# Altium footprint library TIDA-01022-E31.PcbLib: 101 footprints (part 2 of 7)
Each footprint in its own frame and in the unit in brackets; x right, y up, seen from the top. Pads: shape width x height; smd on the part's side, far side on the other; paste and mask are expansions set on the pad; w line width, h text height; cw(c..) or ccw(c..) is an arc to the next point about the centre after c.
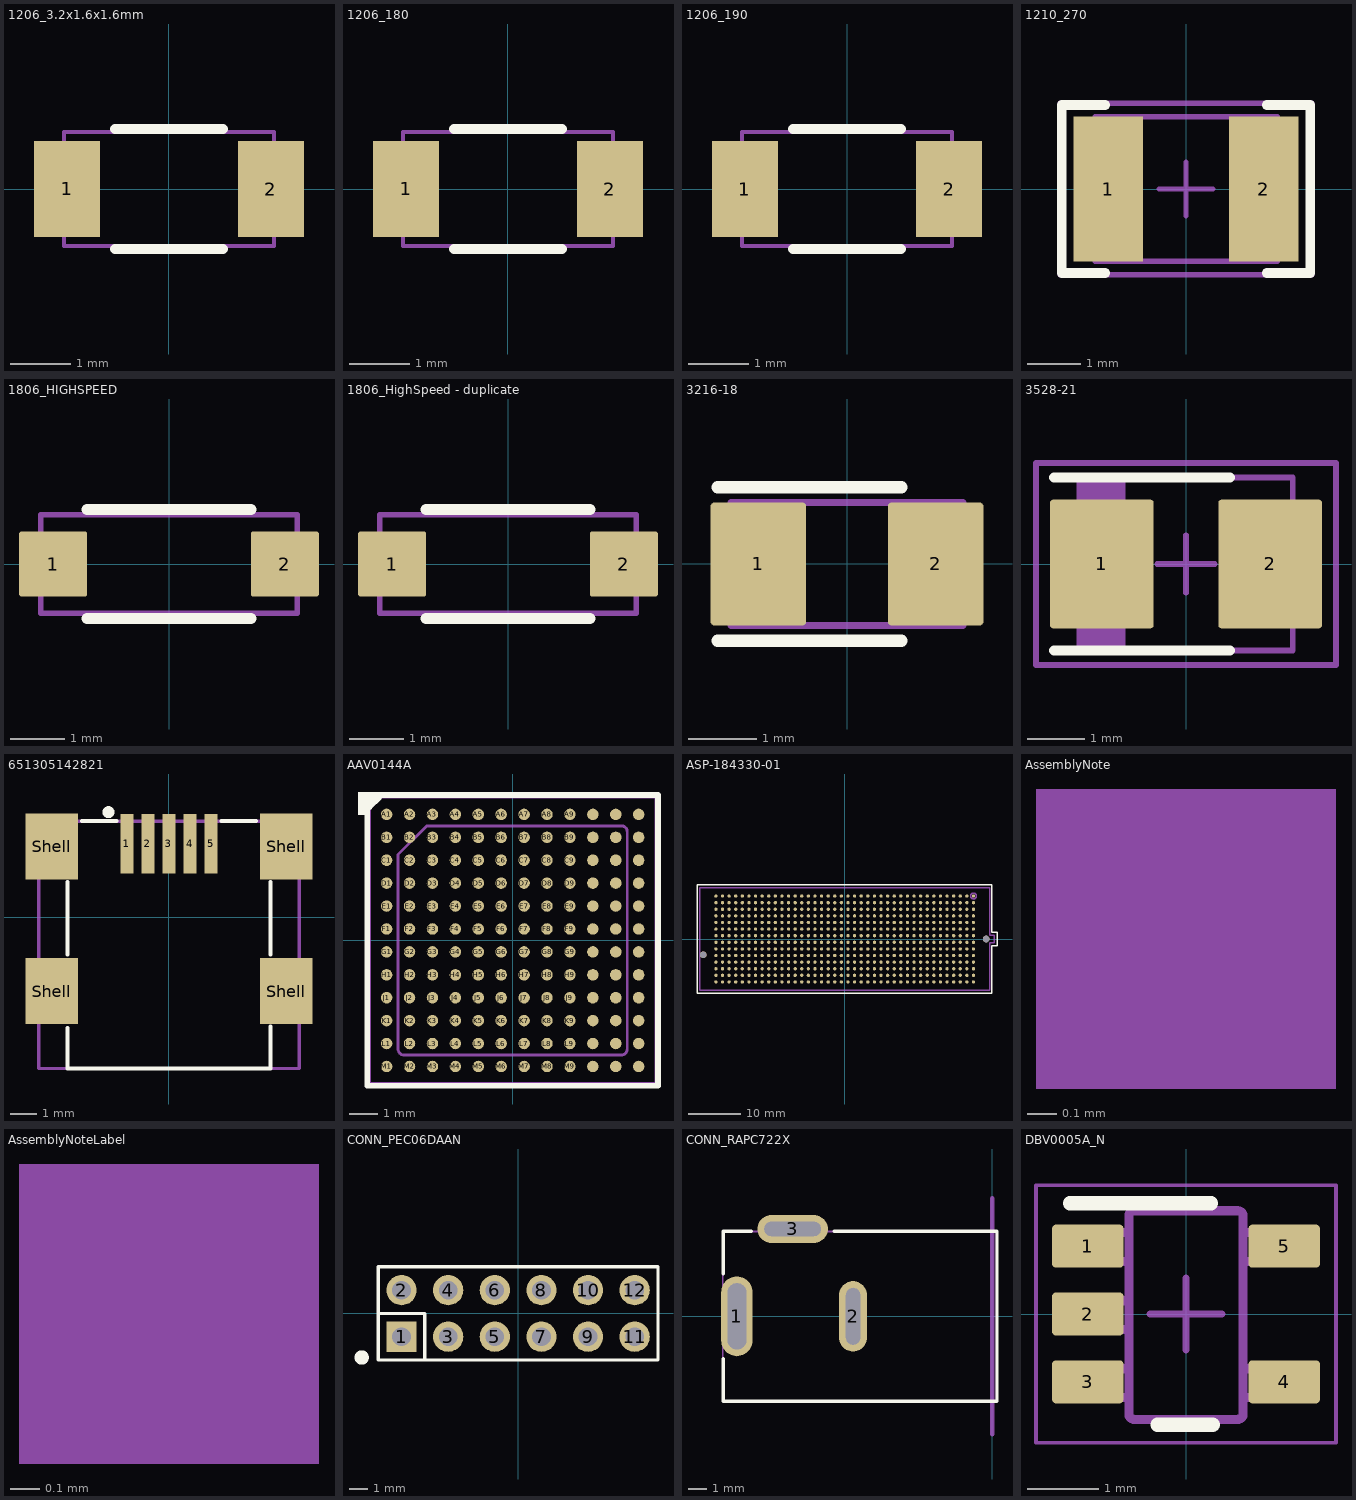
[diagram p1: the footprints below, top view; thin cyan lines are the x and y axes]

## 1206_3.2x1.6x1.6mm [mm]
pads (2):
  rect 1.1x1.6 smd: 1(-1.7,0) 2(1.7,0)
Top Overlay:
  lines w0.17: -0.9,-1 0.9,-1 ; -0.9,1 0.9,1
Mechanical 5:
  lines w0.07: -1.75,-0.95 -1.75,0.95 1.75,0.95 1.75,-0.95 -1.75,-0.95
  text ".Designator" at 0.709,0.188 h0.51
3D body: height 1.8, standoff 0, extent 1.301,-0.949 1.749,0.949
3D body: height 1.8, standoff 0, extent -1.299,-0.949 1.299,0.949
3D body: height 1.8, standoff 0, extent -1.749,-0.949 -1.301,0.949

## 1206_180 [mm] "1206_180"
height 1.8
pads (2):
  rect 1.1x1.6 smd: 1(-1.7,0) 2(1.7,0)
Top Overlay:
  lines w0.17: -0.9,-1 0.9,-1 ; -0.9,1 0.9,1
Mechanical 5:
  lines w0.07: -1.75,-0.95 -1.75,0.95 1.75,0.95 1.75,-0.95 -1.75,-0.95
  text ".Designator" at 0.709,0.188 h0.51
3D body: height 1.8, standoff 0, extent 1.301,-0.949 1.749,0.949
3D body: height 1.8, standoff 0, extent -1.299,-0.949 1.299,0.949
3D body: height 1.8, standoff 0, extent -1.749,-0.949 -1.301,0.949

## 1206_190 [mm] "1206_190"
height 1.9
pads (2):
  rect 1.1x1.6 smd: 1(-1.7,0) 2(1.7,0)
Top Overlay:
  lines w0.17: -0.9,-1 0.9,-1 ; -0.9,1 0.9,1
Mechanical 5:
  lines w0.07: -1.75,-0.95 -1.75,0.95 1.75,0.95 1.75,-0.95 -1.75,-0.95
  text ".Designator" at -0.771,-0.172 h0.51
3D body: height 1.9, standoff 0, extent 1.301,-0.949 1.749,0.949
3D body: height 1.9, standoff 0, extent -1.299,-0.949 1.299,0.949
3D body: height 1.9, standoff 0, extent -1.749,-0.949 -1.301,0.949

## 1210_270 [mm] "1210"
height 2.7
pads (2):
  rect 1.3x2.7 smd: 1(-1.45,0) 2(1.45,0)
Top Overlay:
  lines w0.178: -1.511,-1.568 -2.316,-1.568 -2.316,1.568 -1.511,1.568 ; 1.511,-1.568 2.316,-1.568 2.316,1.568 1.511,1.568
Mechanical 5:
  lines w0.1: -1.7,-1.35 1.7,-1.35 1.7,1.35 -1.7,1.35 -1.7,-1.35
  text ".Designator" at -0.838,-0.229 h0.51
Mechanical 13:
  lines w0.1: -1.2,-1.35 -1.2,1.35 ; 1.2,-1.35 1.2,1.35 ; -1.7,-1.35 -1.7,1.35 1.7,1.35 1.7,-1.35 -1.7,-1.35
Mechanical 15:
  lines w0.1: -0.5,0 0.5,0 ; 0,-0.5 0,0.5 ; -2.35,-1.6 -2.35,1.6 2.35,1.6 2.35,-1.6 -2.35,-1.6
3D body: height 2.7, standoff 0, extent -1.699,-1.349 -1.201,1.349
3D body: height 2.7, standoff 0, extent -1.199,-1.349 1.199,1.349
3D body: height 2.7, standoff 0, extent 1.201,-1.349 1.699,1.349

## 1806_HIGHSPEED [mm] "Wurth recommended land pattern"
height 1.85
pads (2):
  rrect8% 1.25x1.2 smd: 1(-2.125,0) 2(2.125,0)
Top Overlay:
  lines w0.2: -1.5,-1 1.5,-1 ; -1.5,1 1.5,1
Mechanical 5:
  lines w0.1: -2.35,-0.9 2.35,-0.9 2.35,0.9 -2.35,0.9 -2.35,-0.9
  text ".Designator" at -0.441,-0.197 h0.51
3D body "1806.stp": height 1.61, standoff 0.01, extent -2.25,-0.8 2.25,0.8

## 1806_HighSpeed - duplicate [mm]
pads (2):
  rrect8% 1.25x1.2 smd: 1(-2.125,0) 2(2.125,0)
Top Overlay:
  lines w0.2: -1.5,-1 1.5,-1 ; -1.5,1 1.5,1
Mechanical 5:
  lines w0.1: -2.35,-0.9 -2.35,0.9 2.35,0.9 2.35,-0.9 -2.35,-0.9
  text ".Designator" at 1.143,0.178 h0.51
3D body "1806.stp": height 1.61, standoff 0.01, extent -2.25,-0.8 2.25,0.8

## 3216-18 [mm] "Based on AVX recommendation in http://www.avx.com/download/software/literature/AVX-Footprint-Library.pdf"
height 1.8
pads (2):
  rrect7% 1.4x1.8 smd: 1(-1.3,0) 2(1.3,0)
Top Overlay:
  lines w0.178: -1.9,-1.125 0.8,-1.125 ; -1.9,1.125 0.8,1.125
Mechanical 5:
  rectangle: -1.7,-0.9 -1.175,0.9
  lines w0.1: -1.175,-0.9 -1.175,0.9 ; -1.7,-0.9 -1.7,0.9 1.7,0.9 1.7,-0.9 -1.7,-0.9
  text ".Designator" at -0.679,-0.154 h0.51
3D body "3216-18.stp": height 1.82, standoff 0.01, extent -1.7,-0.9 1.7,0.9

## 3528-21 [mm] "Medium Density IPC, based on Kemet datasheet 2016-10-20"
height 2.1
pads (2):
  rrect6% 1.8x2.23 smd: 1(-1.46,0) 2(1.46,0)
Top Overlay:
  lines w0.178: -2.286,-1.5 0.762,-1.5 ; -2.286,1.5 0.762,1.5
Mechanical 5:
  rectangle: -1.85,-1.502 -1.1,1.498
  lines w0.1: -1.1,-1.5 -1.1,1.5 ; -1.85,-1.5 -1.85,1.5 1.85,1.5 1.85,-1.5 -1.85,-1.5
  text ".Designator" at -0.472,-0.201 h0.51
Mechanical 15:
  lines w0.1: -0.5,0 0.5,0 ; 0,-0.5 0,0.5 ; -2.6,-1.75 2.6,-1.75 2.6,1.75 -2.6,1.75 -2.6,-1.75
3D body "3528-21.stp": height 2.12, standoff 0.01, extent -1.85,-1.5 1.85,1.5

## 651305142821 [mm] "5 pins"
height 4
pads (9):
  rect 0.5x2.25 smd: 1(-1.6,2.8) 2(-0.8,2.8) 3(0,2.8) 4(0.8,2.8) 5(1.6,2.8)
  rect 2x2.5 smd: Shell(-4.45,-2.8) Shell(-4.45,2.7) Shell(4.45,-2.8) Shell(4.45,2.7)
Top Overlay:
  circle w0.254: c-2.3,4 r0.1
  lines w0.152: -3.85,-4.2 -3.85,-5.74 3.85,-5.74 ; -3.85,-1.4 -3.85,1.35 ; -3.3,3.66 -1.99,3.66 ; 2,3.66 3.3,3.66 ; 3.85,-5.74 3.85,-4.15 ; 3.85,-1.4 3.85,1.35
Mechanical 13:
  lines w0.127: -4.95,-5.74 -4.95,3.66 4.95,3.66 4.95,-5.74 -4.95,-5.74
3D body "651305142821.stp": height -0.4, standoff -4.5, extent -4.95,-5.74 4.95,3.66

## AAV0144A [mm] "BGA, 144-Leads, Body 10x10mm, Pitch 0.8mm"
height 1.94
pads (144):
  round 0.4 smd: A1(-4.4,4.4) A2(-3.6,4.4) A3(-2.8,4.4) A4(-2,4.4) A5(-1.2,4.4) A6(-0.4,4.4) A7(0.4,4.4) A8(1.2,4.4) A9(2,4.4) A10(2.8,4.4) A11(3.6,4.4) A12(4.4,4.4) B1(-4.4,3.6) B2(-3.6,3.6) B3(-2.8,3.6) B4(-2,3.6) B5(-1.2,3.6) B6(-0.4,3.6) B7(0.4,3.6) B8(1.2,3.6) B9(2,3.6) B10(2.8,3.6) B11(3.6,3.6) B12(4.4,3.6) C1(-4.4,2.8) C2(-3.6,2.8) C3(-2.8,2.8) C4(-2,2.8) C5(-1.2,2.8) C6(-0.4,2.8) C7(0.4,2.8) C8(1.2,2.8) C9(2,2.8) C10(2.8,2.8) C11(3.6,2.8) C12(4.4,2.8) D1(-4.4,2) D2(-3.6,2) D3(-2.8,2) D4(-2,2) D5(-1.2,2) D6(-0.4,2) D7(0.4,2) D8(1.2,2) D9(2,2) D10(2.8,2) D11(3.6,2) D12(4.4,2) E1(-4.4,1.2) E2(-3.6,1.2) E3(-2.8,1.2) E4(-2,1.2) E5(-1.2,1.2) E6(-0.4,1.2) E7(0.4,1.2) E8(1.2,1.2) E9(2,1.2) E10(2.8,1.2) E11(3.6,1.2) E12(4.4,1.2) F1(-4.4,0.4) F2(-3.6,0.4) F3(-2.8,0.4) F4(-2,0.4) F5(-1.2,0.4) F6(-0.4,0.4) F7(0.4,0.4) F8(1.2,0.4) F9(2,0.4) F10(2.8,0.4) F11(3.6,0.4) F12(4.4,0.4) G1(-4.4,-0.4) G2(-3.6,-0.4) G3(-2.8,-0.4) G4(-2,-0.4) G5(-1.2,-0.4) G6(-0.4,-0.4) G7(0.4,-0.4) G8(1.2,-0.4) G9(2,-0.4) G10(2.8,-0.4) G11(3.6,-0.4) G12(4.4,-0.4) H1(-4.4,-1.2) H2(-3.6,-1.2) H3(-2.8,-1.2) H4(-2,-1.2) H5(-1.2,-1.2) H6(-0.4,-1.2) H7(0.4,-1.2) H8(1.2,-1.2) H9(2,-1.2) H10(2.8,-1.2) H11(3.6,-1.2) H12(4.4,-1.2) J1(-4.4,-2) J2(-3.6,-2) J3(-2.8,-2) J4(-2,-2) J5(-1.2,-2) J6(-0.4,-2) J7(0.4,-2) J8(1.2,-2) J9(2,-2) J10(2.8,-2) J11(3.6,-2) J12(4.4,-2) K1(-4.4,-2.8) K2(-3.6,-2.8) K3(-2.8,-2.8) K4(-2,-2.8) K5(-1.2,-2.8) K6(-0.4,-2.8) K7(0.4,-2.8) K8(1.2,-2.8) K9(2,-2.8) K10(2.8,-2.8) K11(3.6,-2.8) K12(4.4,-2.8) L1(-4.4,-3.6) L2(-3.6,-3.6) L3(-2.8,-3.6) L4(-2,-3.6) L5(-1.2,-3.6) L6(-0.4,-3.6) L7(0.4,-3.6) L8(1.2,-3.6) L9(2,-3.6) L10(2.8,-3.6) L11(3.6,-3.6) L12(4.4,-3.6) M1(-4.4,-4.4) M2(-3.6,-4.4) M3(-2.8,-4.4) M4(-2,-4.4) M5(-1.2,-4.4) M6(-0.4,-4.4) M7(0.4,-4.4) M8(1.2,-4.4) M9(2,-4.4) M10(2.8,-4.4) M11(3.6,-4.4) M12(4.4,-4.4)
Top Overlay:
  rectangle: -5.4,4.375 -5,5.175
  region: -4.656,5 -5,4.656 -5,5
  lines w0.2: -5,4.656 -4.656,5 ; -5.075,-5.075 -5.075,5.075 5.075,5.075 5.075,-5.075 -5.075,-5.075
Mechanical 5:
  lines w0.1: -5,-5 -5,5 5,5 5,-5 -5,-5 ; -4,-3.8 ccw(c-3.8,-3.8) -3.8,-4 3.8,-4 ccw(c3.8,-3.8) 4,-3.8 4,3.8 ccw(c3.8,3.8) 3.8,4 -3,4 -4,3 -4,-3.8
  text ".Designator" at -0.491,-0.185 h0.51
3D body "AAV0144A.stp": height 1.77, standoff 0, extent -5,-5 5,5

## ASP-184330-01 [mil]
height 375.2
pads (562):
  round 25 smd paste+5 mask+2: A1(975,225) A2(925,225) A3(875,225) A4(825,225) A5(775,225) A6(725,225) A7(675,225) A8(625,225) A9(575,225) A10(525,225) A11(475,225) A12(425,225) A13(375,225) A14(325,225) A15(275,225) A16(225,225) A17(175,225) A18(125,225) A19(75,225) A20(25,225) A21(-25,225) A22(-75,225) A23(-125,225) A24(-175,225) A25(-225,225) A26(-275,225) A27(-325,225) A28(-375,225) A29(-425,225) A30(-475,225) A31(-525,225) A32(-575,225) A33(-625,225) A34(-675,225) A35(-725,225) A36(-775,225) A37(-825,225) A38(-875,225) A39(-925,225) A40(-975,225) B1(975,175) B2(925,175) B3(875,175) B4(825,175) B5(775,175) B6(725,175) B7(675,175) B8(625,175) B9(575,175) B10(525,175) B11(475,175) B12(425,175) B13(375,175) B14(325,175) B15(275,175) B16(225,175) B17(175,175) B18(125,175) B19(75,175) B20(25,175) B21(-25,175) B22(-75,175) B23(-125,175) B24(-175,175) B25(-225,175) B26(-275,175) B27(-325,175) B28(-375,175) B29(-425,175) B30(-475,175) B31(-525,175) B32(-575,175) B33(-625,175) B34(-675,175) B35(-725,175) B36(-775,175) B37(-825,175) B38(-875,175) B39(-925,175) B40(-975,175) C1(975,125) C2(925,125) C3(875,125) C4(825,125) C5(775,125) C6(725,125) C7(675,125) C8(625,125) C9(575,125) C10(525,125) C11(475,125) C12(425,125) C13(375,125) C14(325,125) C15(275,125) C16(225,125) C17(175,125) C18(125,125) C19(75,125) C20(25,125) C21(-25,125) C22(-75,125) C23(-125,125) C24(-175,125) C25(-225,125) C26(-275,125) C27(-325,125) C28(-375,125) C29(-425,125) C30(-475,125) C31(-525,125) C32(-575,125) C33(-625,125) C34(-675,125) C35(-725,125) C36(-775,125) C37(-825,125) C38(-875,125) C39(-925,125) C40(-975,125) D1(975,75) D2(925,75) D3(875,75) D4(825,75) D5(775,75) D6(725,75) D7(675,75) D8(625,75) D9(575,75) D10(525,75) D11(475,75) D12(425,75) D13(375,75) D14(325,75) D15(275,75) D16(225,75) D17(175,75) D18(125,75) D19(75,75) D20(25,75) D21(-25,75) D22(-75,75) D23(-125,75) D24(-175,75) D25(-225,75) D26(-275,75) D27(-325,75) D28(-375,75) D29(-425,75) D30(-475,75) D31(-525,75) D32(-575,75) D33(-625,75) D34(-675,75) D35(-725,75) D36(-775,75) D37(-825,75) D38(-875,75) D39(-925,75) D40(-975,75) E1(975,25) E2(925,25) E3(875,25) E4(825,25) E5(775,25) E6(725,25) E7(675,25) E8(625,25) E9(575,25) E10(525,25) E11(475,25) E12(425,25) E13(375,25) E14(325,25) E15(275,25) E16(225,25) E17(175,25) E18(125,25) E19(75,25) E20(25,25) E21(-25,25) E22(-75,25) E23(-125,25) E24(-175,25) E25(-225,25) E26(-275,25) E27(-325,25) E28(-375,25) E29(-425,25) E30(-475,25) E31(-525,25) E32(-575,25) E33(-625,25) E34(-675,25) E35(-725,25) E36(-775,25) E37(-825,25) E38(-875,25) E39(-925,25) E40(-975,25) F1(975,-25) F2(925,-25) F3(875,-25) F4(825,-25) F5(775,-25) F6(725,-25) F7(675,-25) F8(625,-25) F9(575,-25) F10(525,-25) F11(475,-25) F12(425,-25) F13(375,-25) F14(325,-25) F15(275,-25) F16(225,-25) F17(175,-25) F18(125,-25) F19(75,-25) F20(25,-25) F21(-25,-25) F22(-75,-25) F23(-125,-25) F24(-175,-25) F25(-225,-25) F26(-275,-25) F27(-325,-25) F28(-375,-25) F29(-425,-25) F30(-475,-25) F31(-525,-25) F32(-575,-25) F33(-625,-25) F34(-675,-25) F35(-725,-25) F36(-775,-25) F37(-825,-25) F38(-875,-25) F39(-925,-25) F40(-975,-25) G1(975,-75) G2(925,-75) G3(875,-75) G4(825,-75) G5(775,-75) G6(725,-75) G7(675,-75) G8(625,-75) G9(575,-75) G10(525,-75) G11(475,-75) G12(425,-75) G13(375,-75) G14(325,-75) G15(275,-75) G16(225,-75) G17(175,-75) G18(125,-75) G19(75,-75) G20(25,-75) G21(-25,-75) G22(-75,-75) G23(-125,-75) G24(-175,-75) G25(-225,-75) G26(-275,-75) G27(-325,-75) G28(-375,-75) G29(-425,-75) G30(-475,-75) G31(-525,-75) G32(-575,-75) G33(-625,-75) G34(-675,-75) G35(-725,-75) G36(-775,-75) G37(-825,-75) G38(-875,-75) G39(-925,-75) G40(-975,-75) H1(975,-125) H2(925,-125) H3(875,-125) H4(825,-125) H5(775,-125) H6(725,-125) H7(675,-125) H8(625,-125) H9(575,-125) H10(525,-125) H11(475,-125) H12(425,-125) H13(375,-125) H14(325,-125) H15(275,-125) H16(225,-125) H17(175,-125) H18(125,-125) H19(75,-125) H20(25,-125) H21(-25,-125) H22(-75,-125) H23(-125,-125) H24(-175,-125) H25(-225,-125) H26(-275,-125) H27(-325,-125) H28(-375,-125) H29(-425,-125) H30(-475,-125) H31(-525,-125) H32(-575,-125) H33(-625,-125) H34(-675,-125) H35(-725,-125) H36(-775,-125) H37(-825,-125) H38(-875,-125) H39(-925,-125) H40(-975,-125) J1(975,-175) J2(925,-175) J3(875,-175) J4(825,-175) J5(775,-175) J6(725,-175) J7(675,-175) J8(625,-175) J9(575,-175) J10(525,-175) J11(475,-175) J12(425,-175) J13(375,-175) J14(325,-175) J15(275,-175) J16(225,-175) J17(175,-175) J18(125,-175) J19(75,-175) J20(25,-175) J21(-25,-175) J22(-75,-175) J23(-125,-175) J24(-175,-175) J25(-225,-175) J26(-275,-175) J27(-325,-175) J28(-375,-175) J29(-425,-175) J30(-475,-175) J31(-525,-175) J32(-575,-175) J33(-625,-175) J34(-675,-175) J35(-725,-175) J36(-775,-175) J37(-825,-175) J38(-875,-175) J39(-925,-175) J40(-975,-175) K1(975,-225) K2(925,-225) K3(875,-225) K4(825,-225) K5(775,-225) K6(725,-225) K7(675,-225) K8(625,-225) K9(575,-225) K10(525,-225) K11(475,-225) K12(425,-225) K13(375,-225) K14(325,-225) K15(275,-225) K16(225,-225) K17(175,-225) K18(125,-225) K19(75,-225) K20(25,-225) K21(-25,-225) K22(-75,-225) K23(-125,-225) K24(-175,-225) K25(-225,-225) K26(-275,-225) K27(-325,-225) K28(-375,-225) K29(-425,-225) K30(-475,-225) K31(-525,-225) K32(-575,-225) K33(-625,-225) K34(-675,-225) K35(-725,-225) K36(-775,-225) K37(-825,-225) K38(-875,-225) K39(-925,-225) K40(-975,-225) L1(975,-275) L2(925,-275) L3(875,-275) L4(825,-275) L5(775,-275) L6(725,-275) L7(675,-275) L8(625,-275) L9(575,-275) L10(525,-275) L11(475,-275) L12(425,-275) L13(375,-275) L14(325,-275) L15(275,-275) L16(225,-275) L17(175,-275) L18(125,-275) L19(75,-275) L20(25,-275) L21(-25,-275) L22(-75,-275) L23(-125,-275) L24(-175,-275) L25(-225,-275) L26(-275,-275) L27(-325,-275) L28(-375,-275) L29(-425,-275) L30(-475,-275) L31(-525,-275) L32(-575,-275) L33(-625,-275) L34(-675,-275) L35(-725,-275) L36(-775,-275) L37(-825,-275) L38(-875,-275) L39(-925,-275) L40(-975,-275) M1(975,-325) M2(925,-325) M3(875,-325) M4(825,-325) M5(775,-325) M6(725,-325) M7(675,-325) M8(625,-325) M9(575,-325) M10(525,-325) M11(475,-325) M12(425,-325) M13(375,-325) M14(325,-325) M15(275,-325) M16(225,-325) M17(175,-325) M18(125,-325) M19(75,-325) M20(25,-325) M21(-25,-325) M22(-75,-325) M23(-125,-325) M24(-175,-325) M25(-225,-325) M26(-275,-325) M27(-325,-325) M28(-375,-325) M29(-425,-325) M30(-475,-325) M31(-525,-325) M32(-575,-325) M33(-625,-325) M34(-675,-325) M35(-725,-325) M36(-775,-325) M37(-825,-325) M38(-875,-325) M39(-925,-325) M40(-975,-325) Y1(975,325) Y2(925,325) Y3(875,325) Y4(825,325) Y5(775,325) Y6(725,325) Y7(675,325) Y8(625,325) Y9(575,325) Y10(525,325) Y11(475,325) Y12(425,325) Y13(375,325) Y14(325,325) Y15(275,325) Y16(225,325) Y17(175,325) Y18(125,325) Y19(75,325) Y20(25,325) Y21(-25,325) Y22(-75,325) Y23(-125,325) Y24(-175,325) Y25(-225,325) Y26(-275,325) Y27(-325,325) Y28(-375,325) Y29(-425,325) Y30(-475,325) Y31(-525,325) Y32(-575,325) Y33(-625,325) Y34(-675,325) Y35(-725,325) Y36(-775,325) Y37(-825,325) Y38(-875,325) Y39(-925,325) Y40(-975,325) Z1(975,275) Z2(925,275) Z3(875,275) Z4(825,275) Z5(775,275) Z6(725,275) Z7(675,275) Z8(625,275) Z9(575,275) Z10(525,275) Z11(475,275) Z12(425,275) Z13(375,275) Z14(325,275) Z15(275,275) Z16(225,275) Z17(175,275) Z18(125,275) Z19(75,275) Z20(25,275) Z21(-25,275) Z22(-75,275) Z23(-125,275) Z24(-175,275) Z25(-225,275) Z26(-275,275) Z27(-325,275) Z28(-375,275) Z29(-425,275) Z30(-475,275) Z31(-525,275) Z32(-575,275) Z33(-625,275) Z34(-675,275) Z35(-725,275) Z36(-775,275) Z37(-825,275) Z38(-875,275) Z39(-925,275) Z40(-975,275)
  round 50 hole 50 unplated mask+10: MH1(1070.5,0) MH2(-1070.5,-120)
Top Overlay:
  lines w10: -1118,-409 1115,-409 1115,-50 1153,-50 1153,50 1115,50 1115,409 -1118,409 -1118,-409
Mechanical 5:
  circle w10: c975,325 r22.36
  lines w10: -1098,-389 1098,-389 1098,-30 1133,-30 1133,30 1098,30 1098,389 -1098,389 -1098,-389
  text "J1" at -52.11,0.07 h20

## AssemblyNote [mm] "Assembly Note"
Mechanical 5:
  rectangle: 17.91,100.583 18.926,101.599
  text ".Designator" at 14.072,100.686 h0.51
  text ".Comment" at 19.482,100.813 h0.51

## AssemblyNoteLabel [mm] "Assembly Note for PCB Labels"
Mechanical 5:
  rectangle: 15.799,83.744 16.815,84.76
  text "Install label in silkscreened box after final wash.  Text shall be 8 pt font.  Text shall be per the Label Table in the PDF schematic." at 17.755,83.896 h0.51
  text ".Designator" at 11.913,83.845 h0.51

## CONN_PEC06DAAN [mm] "SULLINS"
height 8.382
pads (12):
  rect 1.65x1.65 hole 1.016 mask+0: 1(-6.35,-1.27)
  round 1.65 hole 1.016 mask+0: 2(-6.35,1.27) 3(-3.81,-1.27) 4(-3.81,1.27) 5(-1.27,-1.27) 6(-1.27,1.27) 7(1.27,-1.27) 8(1.27,1.27) 9(3.81,-1.27) 10(3.81,1.27) 11(6.35,-1.27) 12(6.35,1.27)
Top Overlay:
  circle w0.381: c-8.52,-2.4 r0.203
  lines w0.178: -7.62,0 -5.08,0 -5.08,-2.54 ; -7.62,-2.54 -7.62,2.54 7.62,2.54 7.62,-2.54 -7.62,-2.54
Mechanical 5:
  rectangle: -6.858,-1.778 -5.842,-0.762
  lines w0.076: -7.62,-2.54 -7.62,2.54 7.62,2.54 7.62,-2.54 -7.62,-2.54
  lines w0.127: -7.62,-2.54 7.62,-2.54 7.62,2.54 -7.62,2.54 -7.62,-2.54
  text ".Designator" at 0.279,-1.016 h0.51
3D body: height 8.38, standoff -3.05, extent 3.493,0.953 4.128,1.588
3D body: height 8.38, standoff -3.05, extent 6.033,-1.587 6.668,-0.952
3D body: height 8.38, standoff -3.05, extent 6.033,0.953 6.668,1.588
3D body: height 8.38, standoff -3.05, extent 3.493,-1.587 4.128,-0.952
3D body: height 8.38, standoff -3.05, extent 0.953,0.953 1.588,1.588
3D body: height 8.38, standoff -3.05, extent 0.953,-1.587 1.588,-0.952
3D body: height 8.38, standoff -3.05, extent -1.587,0.953 -0.952,1.588
3D body: height 8.38, standoff -3.05, extent -1.587,-1.587 -0.952,-0.952
3D body: height 8.38, standoff -3.05, extent -4.127,-1.587 -3.492,-0.952
3D body: height 8.38, standoff -3.05, extent -4.127,0.953 -3.492,1.588
3D body: height 8.38, standoff -3.05, extent -6.667,0.953 -6.032,1.588
3D body: height 8.38, standoff -3.05, extent -6.667,-1.587 -6.032,-0.952
3D body: height 2.54, standoff 0, extent -7.619,-2.539 7.619,2.539

## CONN_RAPC722X [mm] "Conn_DC Jack"
height 11.176
pads (3):
  oval 1.7x4.3 hole 1.01 slot 3.56 at 90 deg mask+0.254: 1(-13.741,0)
  oval 1.5x3.8 hole 0.76 slot 3.05 at 90 deg mask+0.254: 2(-7.493,0)
  oval 3.8x1.5 hole 0.76 slot 3.05 at 0 deg mask+0.254: 3(-10.744,4.7)
Top Overlay:
  lines w0.178: -14.478,-2.286 -14.478,-4.572 0.254,-4.572 0.254,4.572 -8.509,4.572 ; -14.478,2.286 -14.478,4.572 -12.954,4.572
Mechanical 2:
  lines w0.254: 0,-6.35 0,6.35
Mechanical 5:
  lines w0.102: -14.505,-4.572 -14.505,4.572 0.227,4.572 0.227,-4.572 -14.505,-4.572
  lines w0.127: -14.443,-1.5 -13.943,-1.5 ; -14.443,1.5 -13.943,1.5 ; -13.543,-1.5 -13.943,-1.5 ; -13.543,1.5 -13.943,1.5 ; -11.993,4.5 -11.993,4.9 -9.493,4.9 -9.493,4.5 ; -13.943,-1.5 -13.943,1.5
  text ".Designator" at -9.55,1.194 h0.51
3D body: height 5.08, standoff -2.54, extent -7.62,-1.397 -7.366,1.397
3D body: height 5.08, standoff -2.54, extent -12.14,4.573 -9.346,4.827
3D body: height 5.08, standoff -2.54, extent -14.06,-1.651 -13.425,1.651
3D body: height 11.18, standoff 0, extent -14.504,-4.571 0.226,4.571

## DBV0005A_N [mm] "SOT23, 5-Leads, Body 2.9x1.6mm, Pitch 0.95mm, Lead Span 2.8mm, IPC Medium Density"
height 1.45
pads (5):
  rrect17% 1x0.6 smd: 1(-1.375,0.95) 2(-1.375,0) 3(-1.375,-0.95) 4(1.375,-0.95) 5(1.375,0.95)
Top Overlay:
  lines w0.2: -1.625,1.55 0.35,1.55 ; -0.4,-1.55 0.375,-1.55
Mechanical 5:
  lines w0.127: -0.801,1.371 cw(c-0.725,1.37) -0.725,1.446 ; -0.801,1.37 -0.801,1.371 ; -0.801,1.37 -0.801,-1.399 -0.801,-1.4 ccw(c-0.725,-1.399) -0.725,-1.475 ; -0.725,-1.475 0.723,-1.475 0.724,-1.475 ccw(c0.723,-1.399) 0.799,-1.4 0.799,-1.399 0.799,1.37 ; -0.725,-1.475 -0.725,-1.475 ; -0.725,1.446 -0.725,1.446 ; -0.725,1.446 0.723,1.446 0.724,1.446 cw(c0.723,1.37) 0.799,1.371 ; 0.799,1.37 0.799,1.371 ; -1.423,-1.167 -1.423,-0.767 -1.199,-0.767 -1.105,-0.767 -1.088,-0.767 -0.835,-0.767 -0.801,-0.767 -0.801,-1.167 -0.835,-1.167 -1.088,-1.167 -1.105,-1.167 -1.199,-1.167 -1.423,-1.167 ; -1.423,-0.215 -1.423,0.186 -1.199,0.186 -1.105,0.186 -1.088,0.186 -0.835,0.186 -0.801,0.186 -0.801,-0.215 -0.835,-0.215 -1.088,-0.215 -1.105,-0.215 -1.199,-0.215 -1.423,-0.215 ; -1.423,0.738 -1.423,1.138 -1.199,1.138 -1.105,1.138 -1.088,1.138 -0.835,1.138 -0.801,1.138 -0.801,0.738 -0.835,0.738 -1.088,0.738 -1.105,0.738 -1.199,0.738 -1.423,0.738 ; 0.799,-1.167 0.834,-1.167 1.087,-1.167 1.103,-1.167 1.198,-1.167 1.422,-1.167 1.422,-0.767 1.198,-0.767 1.103,-0.767 1.087,-0.767 0.834,-0.767 0.799,-0.767 0.799,-1.167 ; 0.799,0.738 0.834,0.738 1.087,0.738 1.103,0.738 1.198,0.738 1.422,0.738 1.422,1.138 1.198,1.138 1.103,1.138 1.087,1.138 0.834,1.138 0.799,1.138 0.799,0.738
  text ".Designator" at -0.25,0.95 h0.51
Mechanical 15:
  lines w0.05: -2.1,-1.8 -2.1,1.8 2.1,1.8 2.1,-1.8 -2.1,-1.8
  lines w0.1: -0.5,0 0.5,0 ; 0,-0.5 0,0.5
3D body "DBV0005A.stp": height 1.09, standoff 0, extent -1.422,-1.461 1.423,1.46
